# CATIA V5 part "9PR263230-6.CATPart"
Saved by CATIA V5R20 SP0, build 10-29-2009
Part number: 9PR263230-6
Revision: ANY
Definition: UNKNOWN
Nomenclature: 9PR263230-6
Source: Unknown
Bounding box of the stored display mesh (mm): x -12.35 to 12.35, y -12.162 to 12.162, z 0 to 2.5
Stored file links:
  C:\Users\Utente\Desktop\IO LAVORO\3D X SITO CF\CUMSA\3D files PR.233230\PR 263230\9PR263230-6.CATPart
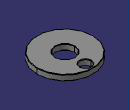
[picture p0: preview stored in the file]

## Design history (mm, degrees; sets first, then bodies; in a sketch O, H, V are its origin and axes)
Body1 "Chaflán2" (main body)
  Solid1: solid without history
